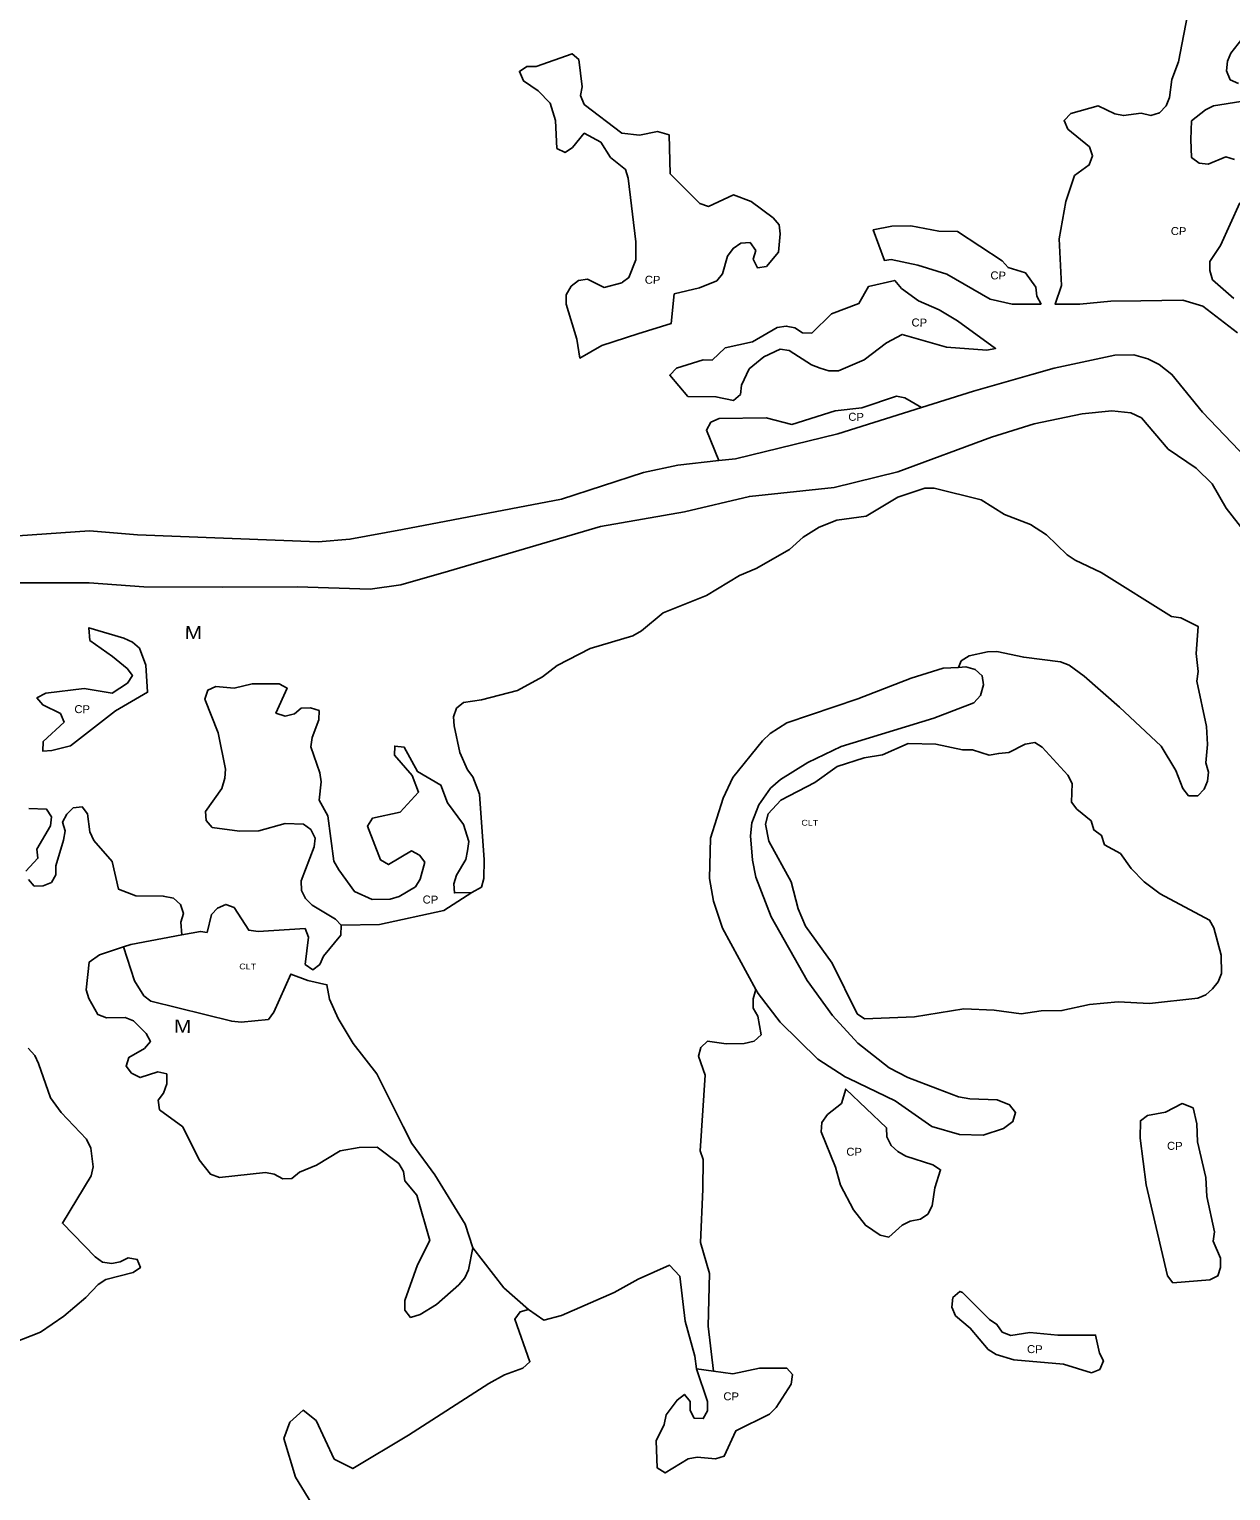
# Model space of a CAD drawing. Extents: x 713589 to 726391, y 7177764 to 7191819.
# Drawn here: x 719111 to 720072, y 7179033 to 7180202 of the extents above; entities that cross this region are included whole.
import ezdxf
from ezdxf.enums import TextEntityAlignment as Align

# ---------------------------------------------------------------- set-up
doc = ezdxf.new("R2010")
doc.units = 0
doc.header["$LTSCALE"] = 2.6
doc.layers.add('63', color=7, linetype='Continuous', lineweight=25)

msp = doc.modelspace()

# ---------------------------------------------------------------- linework, layer by layer
at = {"layer": '63'}
msp.add_line((719644.51, 7179130.25), (719658.14, 7179128.43), dxfattribs=at)
for points in [[(720077.54, 7179959.2), (720049.8, 7179980.55), (720033.67, 7179985.49), (720000.17, 7179984.92), (719976.09, 7179984.51), (719951.4, 7179982.21), (719931.55, 7179982.22), (719936.82, 7179997.16), (719934.85, 7180034.34), (719940.12, 7180064.29), (719947.04, 7180085.02), (719958.88, 7180093.57), (719961.52, 7180100.81), (719959.21, 7180108.05), (719941.78, 7180122.2), (719938.82, 7180129.11), (719944.08, 7180134.71), (719966.13, 7180140.96), (719979.29, 7180134.37), (719986.2, 7180133.05), (720000.35, 7180135.03), (720008.25, 7180133.05), (720015.16, 7180135.35), (720020.43, 7180140.95), (720023.06, 7180147.53), (720025.04, 7180162.01), (720030.31, 7180176.15), (720038.87, 7180220.25)], [(720080.99, 7180194.24), (720072.1, 7180183.06), (720069.47, 7180176.48), (720068.81, 7180168.91), (720071.77, 7180161.67), (720078.35, 7180158.71)], [(720080.32, 7180144.23), (720058.27, 7180140.94), (720052.02, 7180137.65), (720040.83, 7180128.77), (720040.17, 7180113.96), (720040.82, 7180099.48), (720046.75, 7180094.87), (720053.98, 7180094.21), (720068.14, 7180100.13), (720075.05, 7180097.83)], [(720079.32, 7180063.27), (720063.85, 7180029.05), (720055.29, 7180016.22), (720055.29, 7180008.98), (720057.59, 7180001.74), (720074.7, 7179986.6)], [(719824.6, 7179899.48), (719866.16, 7179912.46), (719912.93, 7179925.91), (719930.77, 7179931.04), (719979.26, 7179941.36), (719994.59, 7179941.53), (720005.83, 7179938.35), (720014.99, 7179934.01), (720025.13, 7179925.9), (720049.56, 7179895.8), (720096.48, 7179846.79)], [(719824.6, 7179899.48), (719811.43, 7179907.34), (719804.52, 7179908.66), (719776.87, 7179899.12), (719755.48, 7179896.82), (719720.93, 7179885.97), (719700.2, 7179891.24), (719662.68, 7179890.59), (719656.1, 7179887.63), (719652.48, 7179881.37), (719662.37, 7179857.02)], [(719103.36, 7179759.33), (719158.41, 7179759.27), (719202.15, 7179756.01), (719264.9, 7179755.68), (719325.19, 7179756.01), (719383.3, 7179754.02), (719408.06, 7179757.71), (719446.02, 7179768.58), (719567.74, 7179804.19), (719635.09, 7179816.13), (719686.91, 7179828.34), (719754.8, 7179835.5), (719805.72, 7179848.15), (719880.66, 7179875.89), (719914.8, 7179886.34), (719953.35, 7179894.46), (719977.08, 7179896.86), (719992.21, 7179895.21), (720000.61, 7179891.29), (720021.99, 7179866.24), (720044.52, 7179851.07), (720057.27, 7179838.39), (720068.46, 7179818.89), (720095.39, 7179784.48)], [(719662.37, 7179857.02), (719675.7, 7179858.54), (719757.57, 7179878.54), (719824.6, 7179899.48)], [(719078.16, 7179795.17), (719158.78, 7179800.91), (719197.26, 7179797.72), (719341.69, 7179792.11), (719367.24, 7179794.07), (719409.26, 7179801.8), (719536.54, 7179826.12), (719602.08, 7179847.44), (719629.61, 7179853.29), (719662.37, 7179857.02)], [(719464.7, 7179511.43), (719472.52, 7179515.74), (719474.49, 7179522.65), (719474.5, 7179537.46), (719470.89, 7179590.11), (719465.62, 7179603.93), (719461.35, 7179609.53), (719455.1, 7179623.35), (719450.49, 7179644.74), (719450.16, 7179651.98), (719452.47, 7179658.89), (719458.06, 7179663.5), (719472.54, 7179665.47), (719501.17, 7179673.03), (719521.25, 7179683.89), (719533.1, 7179693.1), (719559.43, 7179706.59), (719593.65, 7179716.78), (719600.56, 7179720.73), (719618.01, 7179735.21), (719652.56, 7179749.02), (719678.89, 7179765.14), (719692.38, 7179770.73), (719719.04, 7179785.87), (719729.9, 7179795.74), (719742.74, 7179803.63), (719756.89, 7179809.22), (719780.25, 7179812.51), (719805.59, 7179827.64), (719827.31, 7179834.88), (719834.88, 7179834.88), (719872.39, 7179825.66), (719891.15, 7179813.81), (719911.88, 7179805.91), (719924.71, 7179797.68), (719941.16, 7179781.55), (719947.74, 7179777.27), (719968.47, 7179767.39), (720024.74, 7179732.17), (720032.3, 7179731.19), (720046.06, 7179724.34), (720044.41, 7179702.62), (720046.05, 7179688.14), (720045.06, 7179680.57), (720052.63, 7179644.37), (720053.61, 7179629.89), (720052.29, 7179615.09), (720054.26, 7179607.85), (720053.61, 7179600.61), (720050.97, 7179594.03), (720045.71, 7179588.76), (720038.47, 7179588.76), (720033.86, 7179594.69), (720028.27, 7179609.17), (720016.43, 7179628.58), (719983.19, 7179659.85), (719954.9, 7179684.54), (719942.72, 7179693.42), (719935.81, 7179696.06), (719906.53, 7179699.68), (719884.81, 7179704.29), (719877.57, 7179703.97), (719862.76, 7179700.68), (719856.51, 7179696.73), (719854.23, 7179691.6)], [(719854.23, 7179691.6), (719842.06, 7179690.82), (719816.29, 7179682.97), (719773.78, 7179666.4), (719716.96, 7179647.08), (719703.42, 7179638.69), (719697.32, 7179632.79), (719673.75, 7179603.38), (719665.87, 7179586.95), (719655.7, 7179554.97), (719654.96, 7179522.69), (719658.26, 7179504.57), (719665.26, 7179483.04), (719692.13, 7179433.71)], [(719692.13, 7179433.71), (719693.81, 7179430.63), (719711.48, 7179407.83), (719741.79, 7179378.17), (719763.54, 7179364.06), (719766.48, 7179362.64), (719803.53, 7179344.75), (719832.88, 7179324.32), (719855.19, 7179317.93), (719873.88, 7179317.39), (719890.16, 7179322.75), (719897.68, 7179328.13), (719899.91, 7179335.41), (719895.16, 7179341.63), (719885.22, 7179345.57), (719863.45, 7179346.26), (719854.29, 7179347.98), (719837.52, 7179354.47), (719813.67, 7179363.44), (719798.68, 7179371.2), (719773.66, 7179390.92), (719753.53, 7179412.99), (719733.23, 7179441.1), (719704.27, 7179492.02), (719692.16, 7179523.59), (719689.27, 7179537.35), (719687.68, 7179556.77), (719688.88, 7179567.06), (719694.35, 7179581.46), (719703.9, 7179595.05), (719711.71, 7179601.76), (719733.66, 7179615.37), (719760.33, 7179628.32), (719834.58, 7179650.91), (719866.66, 7179663.27), (719871.81, 7179669.15), (719874.16, 7179677.69), (719873.28, 7179684.89), (719867.62, 7179689.89), (719860.11, 7179691.97), (719854.23, 7179691.6)], [(719360.24, 7179485.24), (719355.69, 7179490.1), (719336.94, 7179501.29), (719331.67, 7179506.55), (719328.38, 7179513.14), (719328.06, 7179520.7), (719338.59, 7179548.02), (719339.25, 7179554.93), (719335.96, 7179561.84), (719330.04, 7179566.12), (719315.23, 7179566.78), (719294.17, 7179560.86), (719278.7, 7179560.53), (719256.98, 7179563.5), (719252.05, 7179569.09), (719251.72, 7179576.33), (719264.56, 7179594.76), (719267.19, 7179602.98), (719267.52, 7179610.22), (719261.6, 7179639.18), (719251.08, 7179666.17), (719253.38, 7179673.41), (719259.97, 7179676.37), (719274.44, 7179675.05), (719288.92, 7179678.34), (719310.64, 7179678.33), (719316.89, 7179675.04), (719308.01, 7179654.97), (719315.25, 7179652.66), (719322.81, 7179654.31), (719328.08, 7179658.91), (719335.65, 7179659.24), (719342.56, 7179656.94), (719342.23, 7179649.7), (719336.96, 7179635.55), (719335.97, 7179627.98), (719343.21, 7179607.25), (719344.19, 7179600.01), (719342.55, 7179585.2), (719349.45, 7179572.69), (719354.38, 7179536.49), (719358.33, 7179529.58), (719370.83, 7179512.14), (719384.98, 7179505.89), (719399.46, 7179506.21), (719406.7, 7179508.19), (719419.54, 7179516.08), (719423.49, 7179522), (719427.11, 7179535.82), (719422.83, 7179541.42), (719416.58, 7179544.71), (719398.15, 7179533.85), (719391.57, 7179537.48), (719381.37, 7179564.46), (719385.32, 7179571.04), (719407.37, 7179575.64), (719422.18, 7179591.77), (719416.92, 7179604.93), (719402.77, 7179621.39), (719403.1, 7179628.63), (719410.67, 7179627.64), (719421.2, 7179608.22), (719439.95, 7179597.36), (719445.22, 7179583.21), (719458.05, 7179565.76), (719462.32, 7179552.27), (719461.33, 7179544.7), (719460.02, 7179537.79), (719452.45, 7179525.29), (719450.47, 7179518.38), (719450.8, 7179511.14), (719464.7, 7179511.43)], [(719110.22, 7179578.66), (719124.37, 7179578), (719128.32, 7179572.07), (719127.66, 7179564.83), (719116.47, 7179546.08), (719117.45, 7179538.84), (719107.91, 7179528.64)], [(719109.88, 7179521.73), (719114.49, 7179516.46), (719121.73, 7179516.79), (719128.31, 7179519.42), (719131.93, 7179525.67), (719131.93, 7179532.91), (719137.86, 7179553.32), (719139.18, 7179560.88), (719137.2, 7179567.79), (719140.5, 7179574.05), (719145.76, 7179579.31), (719153, 7179579.97), (719157.28, 7179574.37), (719158.92, 7179559.89), (719162.21, 7179552.98), (719177.02, 7179536.2), (719181.95, 7179514.15), (719195.77, 7179508.88), (719217.82, 7179508.55), (719226.04, 7179506.9), (719231.64, 7179501.96), (719233.94, 7179494.72), (719231.96, 7179487.81), (719232.74, 7179477.5)], [(719360.24, 7179485.24), (719390.78, 7179485.75), (719442.44, 7179496.92), (719464.7, 7179511.43)], [(719232.74, 7179477.5), (719247.54, 7179480.27), (719252.91, 7179479.56), (719256.31, 7179493.73), (719261.25, 7179499), (719267.83, 7179501.96), (719274.41, 7179499.32), (719286.26, 7179481.22), (719293.83, 7179480.23), (719331.34, 7179482.53), (719333.97, 7179475.62), (719331.34, 7179453.9), (719337.59, 7179449.62), (719343.18, 7179453.9), (719346.14, 7179460.48), (719359.97, 7179477.26), (719360.24, 7179485.24)], [(719185.94, 7179467.91), (719191.78, 7179469.83), (719232.74, 7179477.5)], [(719185.94, 7179467.91), (719166.75, 7179461.6), (719158.58, 7179455.79), (719156.14, 7179433.46), (719158.12, 7179426.55), (719165.35, 7179413.72), (719172.26, 7179411.08), (719187.4, 7179411.41), (719193.98, 7179408.78), (719204.18, 7179398.57), (719207.47, 7179392.32), (719202.86, 7179386.73), (719190.36, 7179379.49), (719188.05, 7179372.58), (719192.33, 7179366.99), (719199.24, 7179363.36), (719213.39, 7179367.97), (719220.63, 7179366.32), (719220.63, 7179358.42), (719217.99, 7179350.86), (719213.71, 7179345.26), (719214.7, 7179337.69), (719233.45, 7179323.87), (719246.61, 7179297.54), (719255.5, 7179286.02), (719262.73, 7179283.39), (719299.59, 7179287.33), (719306.5, 7179286.01), (719313.41, 7179282.39), (719320.65, 7179282.72), (719326.9, 7179287.66), (719340.4, 7179293.25), (719359.48, 7179304.76), (719374.62, 7179307.39), (719389.1, 7179307.72), (719406.21, 7179294.55), (719410.16, 7179288.3), (719411.14, 7179280.73), (719420.69, 7179269.21), (719431.21, 7179233.01), (719421.33, 7179213.6), (719411.13, 7179184.97), (719411.13, 7179177.4), (719415.73, 7179171.48), (719423.3, 7179173.78), (719436.47, 7179181.68), (719454.24, 7179197.47), (719459.18, 7179203.06), (719462.14, 7179209.64), (719465.5, 7179227.25)], [(719465.5, 7179227.25), (719459.51, 7179246.17), (719435.17, 7179285.66), (719416.74, 7179310.67), (719409.84, 7179324.17), (719388.78, 7179366.29), (719369.7, 7179390.65), (719357.86, 7179410.72), (719350.95, 7179426.19), (719348.78, 7179437.66), (719333.38, 7179440.98), (719319.84, 7179446.19), (719306.19, 7179415.67), (719301.92, 7179409.75), (719280.2, 7179407.77), (719272.63, 7179408.43), (719207.8, 7179424.57), (719202.21, 7179428.85), (719194.64, 7179440.7), (719185.94, 7179467.91)], [(719692.13, 7179433.71), (719689.95, 7179426.26), (719689.95, 7179419.02), (719693.57, 7179412.44), (719696.2, 7179397.63), (719690.6, 7179392.37), (719682.71, 7179390.72), (719668.23, 7179390.4), (719653.42, 7179392.38), (719648.15, 7179387.44), (719646.18, 7179380.53), (719651.44, 7179365.39), (719647.48, 7179304.84), (719649.78, 7179297.93), (719649.51, 7179274.13), (719647.74, 7179231.33), (719654.97, 7179206.65), (719653.98, 7179164.53), (719658.14, 7179128.43)], [(719084.68, 7179146.2), (719119.57, 7179159.68), (719138.33, 7179172.51), (719155.77, 7179187.32), (719165.64, 7179197.85), (719171.9, 7179201.8), (719193.62, 7179207.39), (719199.54, 7179211.33), (719196.91, 7179217.92), (719189.67, 7179219.23), (719183.42, 7179215.94), (719176.51, 7179214.63), (719169.27, 7179215.62), (719163.34, 7179219.9), (719137.02, 7179246.88), (719160.06, 7179284.72), (719161.71, 7179291.96), (719159.74, 7179306.77), (719156.45, 7179314.01), (719136.05, 7179335.4), (719127.5, 7179347.25), (719117.96, 7179374.57), (719115, 7179381.15), (719109.72, 7179386.9)], [(719465.5, 7179227.25), (719490.44, 7179195.16), (719510.22, 7179177.85)], [(719644.51, 7179130.25), (719643.11, 7179140.51), (719635.55, 7179168.48), (719631.28, 7179204.35), (719622.94, 7179213.23), (719597.77, 7179202.18), (719578.68, 7179191.33), (719536.56, 7179172.91), (719522.41, 7179169.29), (719510.24, 7179177.85), (719510.22, 7179177.85)], [(719510.22, 7179177.85), (719503.32, 7179175.87), (719499.05, 7179169.95), (719511.22, 7179136.05), (719505.62, 7179130.79), (719490.81, 7179125.53), (719478.31, 7179118.62), (719414.13, 7179077.17), (719369.6, 7179050.51), (719354.56, 7179058.09), (719340.09, 7179089.03), (719329.89, 7179097.26), (719319.03, 7179087.71), (719314.42, 7179074.55), (719323.63, 7179043.62), (719372.98, 7178962.99)], [(719658.14, 7179128.43), (719673.72, 7179126.35), (719695.11, 7179130.95), (719716.83, 7179130.95), (719721.43, 7179125.68), (719720.44, 7179118.12), (719708.26, 7179099.36), (719703, 7179094.1), (719676.01, 7179080.61), (719666.79, 7179060.54), (719659.88, 7179058.23), (719645.08, 7179059.55), (719637.84, 7179058.24), (719619.41, 7179047.05), (719613.15, 7179051), (719612.17, 7179072.72), (719618.75, 7179085.88), (719620.4, 7179093.45), (719628.96, 7179105.3), (719634.88, 7179109.9), (719639.49, 7179104.31), (719639.49, 7179097.07), (719642.78, 7179090.82), (719650.02, 7179090.49), (719653.31, 7179096.74), (719653.31, 7179104.31), (719644.51, 7179130.25)]]:
    msp.add_lwpolyline(points, dxfattribs=at)
for points in [[(719551.83, 7180149.25), (719554.79, 7180142.01), (719584.73, 7180118.97), (719598.88, 7180117.33), (719613.37, 7180120.29), (719622.58, 7180117.65), (719623.6, 7180086.35), (719647.25, 7180062.69), (719654.16, 7180060.39), (719674.23, 7180069.6), (719688.38, 7180064.33), (719705.82, 7180051.16), (719710.76, 7180045.57), (719711.41, 7180038.33), (719710.09, 7180023.85), (719700.55, 7180012.34), (719693.31, 7180011.35), (719690.02, 7180018.26), (719691.99, 7180025.17), (719687.39, 7180031.42), (719680.15, 7180031.1), (719673.9, 7180026.82), (719669.29, 7180020.57), (719665.34, 7180006.42), (719660.73, 7180000.82), (719646.91, 7179995.23), (719626.71, 7179990.41), (719624.3, 7179966.83), (719597.66, 7179958.31), (719568.69, 7179949.05), (719551.21, 7179939.03), (719548.84, 7179954.12), (719540.29, 7179982.09), (719540.29, 7179989.66), (719544.24, 7179996.57), (719550.16, 7180001.17), (719557.4, 7180002.16), (719570.56, 7179995.58), (719584.71, 7179999.19), (719585.4, 7179999.72), (719590.31, 7180003.47), (719595.9, 7180017.62), (719595.91, 7180032.1), (719589.99, 7180083.11), (719587.69, 7180090.02), (719575.85, 7180099.56), (719567.95, 7180111.74), (719554.79, 7180118.98), (719545.24, 7180107.46), (719539.32, 7180103.52), (719532.74, 7180106.81), (719531.76, 7180129.19), (719527.48, 7180143.01), (719517.94, 7180152.88), (719506.09, 7180160.78), (719502.8, 7180168.35), (719508.73, 7180172.3), (719516.3, 7180172.3), (719544.93, 7180182.49), (719550.52, 7180177.88), (719553.15, 7180156.17)], [(719920.36, 7179982.22), (719897.11, 7179982.22), (719879.67, 7179986.18), (719844.79, 7180006.26), (719821.76, 7180013.5), (719800.37, 7180017.78), (719795.03, 7180017.23), (719786.05, 7180041.75), (719800.92, 7180044.57), (719816.06, 7180044.89), (719838.43, 7180040.61), (719853.57, 7180040.28), (719889.11, 7180016.91), (719894.04, 7180011.64), (719907.86, 7180007.36), (719916.09, 7179995.84), (719917.07, 7179988.6)], [(719686.71, 7179930.4), (719698.56, 7179939.94), (719711.4, 7179946.19), (719718.64, 7179945.2), (719736.73, 7179933.68), (719743.64, 7179931.05), (719750.55, 7179928.74), (719758.12, 7179928.74), (719778.85, 7179937.62), (719796.63, 7179951.11), (719809.13, 7179958.02), (719844.67, 7179947.81), (719876.92, 7179945.5), (719883.95, 7179946.74), (719853.34, 7179968.75), (719838.9, 7179977.69), (719822.25, 7179984.84), (719808.68, 7179994.64), (719803.3, 7180001.23), (719782.16, 7179996.2), (719774.58, 7179982.71), (719752.53, 7179974.48), (719736.74, 7179959.02), (719729.5, 7179959.35), (719723.25, 7179963.3), (719716.34, 7179964.62), (719709.1, 7179963.63), (719689.35, 7179952.12), (719667.63, 7179947.19), (719657.1, 7179937.31), (719649.86, 7179937.65), (719628.47, 7179931.07), (719623.2, 7179925.47), (719637.68, 7179908.36), (719660.05, 7179908.03), (719674.2, 7179905.06), (719679.8, 7179910), (719680.46, 7179917.24)], [(719135.45, 7179654.6), (719121.3, 7179661.52), (719116.69, 7179667.11), (719123.93, 7179671.06), (719154.54, 7179674.67), (719176.92, 7179671.05), (719189.09, 7179678.95), (719193.04, 7179685.2), (719188.77, 7179690.79), (719177.25, 7179700.34), (719159.15, 7179713.17), (719158.35, 7179723.25), (719186.14, 7179714.81), (719193.05, 7179711.85), (719198.64, 7179706.91), (719203.9, 7179693.42), (719205.22, 7179671.7), (719179.55, 7179656.9), (719143.67, 7179628.93), (719128.53, 7179624.99), (719121.29, 7179624.66), (719121.62, 7179632.23), (719138.41, 7179647.69)], [(719992.39, 7179530.53), (719983.83, 7179542.7), (719971, 7179549.62), (719968.7, 7179557.18), (719962.45, 7179561.46), (719960.47, 7179568.7), (719948.96, 7179578.25), (719944.68, 7179583.84), (719945.34, 7179598.65), (719941.72, 7179605.23), (719921.32, 7179627.61), (719915.4, 7179631.56), (719907.5, 7179630.25), (719894.67, 7179623.34), (719886.44, 7179622.68), (719878.87, 7179621.37), (719865.38, 7179625.65), (719857.48, 7179625.65), (719836.09, 7179630.26), (719814.05, 7179630.59), (719793.31, 7179621.71), (719778.83, 7179619.08), (719757.11, 7179612.18), (719739.34, 7179599.35), (719712.03, 7179585.2), (719701.82, 7179574.34), (719699.73, 7179566.11), (719702.48, 7179552.62), (719720.24, 7179520.04), (719725.83, 7179498.32), (719731.75, 7179484.5), (719753.14, 7179454.88), (719773.2, 7179414.4), (719779.13, 7179410.45), (719818.94, 7179412.09), (719858.43, 7179418.34), (719882.79, 7179417.34), (719904.5, 7179414.38), (719920.3, 7179416.68), (719937.08, 7179417.01), (719959.13, 7179421.94), (719982.17, 7179423.91), (720007.18, 7179422.59), (720045.68, 7179426.86), (720052.26, 7179429.49), (720057.53, 7179434.43), (720062.13, 7179440.02), (720064.77, 7179446.6), (720064.44, 7179461.41), (720058.52, 7179483.13), (720055.23, 7179489.38), (720015.75, 7179510.45), (720002.91, 7179519.99)], [(719809.04, 7179245.25), (719798.51, 7179235.71), (719791.6, 7179237.36), (719779.76, 7179245.26), (719770.22, 7179257.44), (719759.69, 7179277.18), (719755.74, 7179291.66), (719744.23, 7179319.96), (719744.89, 7179327.53), (719749.5, 7179333.78), (719760.69, 7179342.67), (719764.02, 7179354.16), (719796.55, 7179323.25), (719796.88, 7179316.01), (719800.5, 7179309.09), (719805.76, 7179304.16), (719812.01, 7179300.54), (719833.73, 7179293.62), (719839.98, 7179289.67), (719835.37, 7179275.19), (719833.07, 7179260.72), (719829.78, 7179254.13), (719823.85, 7179250.19), (719815.63, 7179248.54)], [(720055.51, 7179201.44), (720025.89, 7179199.15), (720021.62, 7179204.74), (720004.52, 7179277.47), (719999.59, 7179314.98), (719999.92, 7179328.8), (720005.51, 7179333.08), (720019.99, 7179335.71), (720033.16, 7179342.62), (720042.06, 7179339.12), (720045, 7179326.49), (720045.66, 7179312.01), (720052.23, 7179283.38), (720052.89, 7179268.25), (720059.14, 7179239.94), (720058.15, 7179232.38), (720064.07, 7179218.88), (720064.07, 7179211.31), (720061.76, 7179204.73)], [(719960.72, 7179127.09), (719938.35, 7179134), (719898.53, 7179137.63), (719884.38, 7179141.91), (719878.13, 7179145.86), (719863.65, 7179162.98), (719851.81, 7179172.85), (719848.85, 7179179.76), (719849.84, 7179187.33), (719855.43, 7179192.26), (719857.54, 7179191.48), (719879.12, 7179169.88), (719885.04, 7179165.93), (719889.32, 7179159.68), (719896.23, 7179157.05), (719911.37, 7179159.35), (719933.75, 7179157.37), (719964.02, 7179157.36), (719966.98, 7179142.88), (719970.27, 7179136.63), (719967.31, 7179129.72)]]:
    msp.add_lwpolyline(points, close=True, dxfattribs=at)

# ---------------------------------------------------------------- texts
for s, height, width, p in [('CP', 6.4, 1.05, (720030.36, 7180037.42)), ('CP', 6.4, 1.05, (719886.01, 7180001.94)), ('CP', 6.4, 1.05, (719609.38, 7179998.46)), ('CP', 6.4, 1.05, (719822.84, 7179964.27)), ('CP', 6.4, 1.05, (719772.24, 7179888.81)), ('M', 10.4, 1.2, (719241.83, 7179714.28)), ('CP', 6.4, 1.05, (719152.85, 7179654.93)), ('CLT', 4.64, 1.15, (719735.24, 7179564.87)), ('CP', 6.4, 1.05, (719431.58, 7179502.58)), ('CLT', 4.64, 1.15, (719285.34, 7179449.89)), ('M', 10.4, 1.2, (719233.24, 7179399.22)), ('CP', 6.4, 1.05, (719770.68, 7179300.8)), ('CP', 6.4, 1.05, (720027.34, 7179305.52)), ('CP', 6.4, 1.05, (719915.29, 7179142.88)), ('CP', 6.4, 1.05, (719672.28, 7179105.11))]:
    msp.add_text(s, height=height, rotation=359.062, dxfattribs=dict(at, width=width)).set_placement(p, align=Align.CENTER)

doc.saveas('drawing.dxf')
